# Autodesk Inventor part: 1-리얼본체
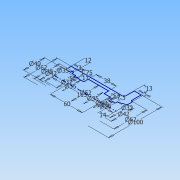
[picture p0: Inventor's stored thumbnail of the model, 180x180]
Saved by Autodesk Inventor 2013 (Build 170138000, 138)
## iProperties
Created: 2016-08
Part Number: 1-리얼본체
Material: Generic
Document SubType Name: Modeling
Designer: Administrator
Density: 1 g/cm^3
Author: Administrator
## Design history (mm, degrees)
sketch "스케치1"
  geometry: L1 (-57.5, 0)-(57.5, 0); L2 (-57.5, 31)-(41.5, 31); L3 (41.5, 31)-(41.5, 50); L4 (41.5, 50)-(54.5, 50); L5 (54.5, 50)-(54.5, 31); L6 (54.5, 31)-(57.5, 31); L7 (57.5, 21)-(57.5, 31); L8 (-57.5, 31)-(-57.5, 21); L9 (-57.5, 21)-(-48.5, 21); L10 (-48.5, 21)-(-48.5, 24); L11 (-48.5, 24)-(-45.5, 24); L12 (-45.5, 24)-(-45.5, 20); L13 (-45.5, 20)-(-38.25, 20); L14 (-38.25, 20)-(-38.25, 17.5); L15 (-38.25, 17.5)-(-33.25, 17.5); L16 (-33.25, 17.5)-(-33.25, 18.5); L17 (-31.5, 18.5)-(-31.5, 17.5); L18 (-31.5, 17.5)-(-20.5, 17.5); L19 (-20.5, 17.5)-(-20.5, 26); L20 (-20.5, 26)-(17.5, 26); L21 (17.5, 26)-(17.5, 17.5); L22 (17.5, 17.5)-(28.5, 17.5); L23 (28.5, 17.5)-(28.5, 16.5); L24 (28.5, 16.5)-(33.5, 16.5); L25 (33.5, 16.5)-(33.5, 10); L26 (33.5, 10)-(36.2, 10); L27 (36.2, 10)-(36.2, 12.5); L28 (36.2, 12.5)-(43.5, 12.5); L29 (43.5, 12.5)-(43.5, 16); L30 (43.5, 16)-(57.5, 21); L31 (-33.25, 18.5)-(-31.5, 18.5); 2 further points
  constraints: 62 end point, 22 parallel, 6 perpendicular, 2 horizontal, 2 vertical alignment, 1 coincident, 1 midpoint
  dimensions: "d0" = 115 distance of L1.start L1.end; "d2" = 62 diameter of L2 L1; "d3" = 100 diameter of L4 L1; "d4" = 13 distance of L3.end L4.end; "d5" = 3 distance between parallel lines of L5 L7; "d6" = 62 diameter of L6 L1; "d7" = 52 diameter of L20 L1; "d8" = 42 diameter of L9 L1; "d9" = 48 diameter of L11 L1; "d12" = 40 diameter of L13 L1; "d13" = 35 diameter of L15 L1; "d15" = 35 diameter of L18 L1; "d19" = 42 diameter of L7.start L1; "d20" = 14 horizontal distance of L29.end L7.start; "d21" = 32 diameter of L29.end L1; "d22" = 7.3 distance of L27.end L28.end; "d23" = 25 diameter of L28 L1; "d24" = 2.7 distance of L25.end L26.end; "d25" = 20 diameter of L26 L1; "d26" = 5 distance of L23.end L24.end; "d27" = 33 diameter of L24 L1; "d28" = 35 diameter of L22 L1; "d29" = 60 distance of L22.end L17.end; "d30" = 38 distance of L19.end L20.end; "d31" = 5 distance of L14.end L15.end; "d32" = 1.75 distance of L16.end L17.start; "d33" = 12 distance between parallel lines of L8 L12; "d34" = 3 distance of L10.end L11.end; "d35" = 37 diameter of L31 L1; "d36" = 11 distance of L17.end L18.end
